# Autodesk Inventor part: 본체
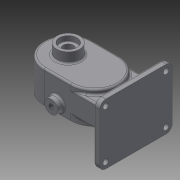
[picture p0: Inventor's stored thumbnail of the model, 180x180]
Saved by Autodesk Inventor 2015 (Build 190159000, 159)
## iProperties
Created: 2020-09
Part Number: 본체
Material: 일반
Document SubType Name: Modeling
Designer: LINEART-SSD.D4.16.07
Density: 1 g/cm^3
Appearance: 기본값
Author: LINEART-SSD.D4.16.07
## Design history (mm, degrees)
sketch "스케치1"
  geometry: L1 (0, 0)-(-44, 0); L2 (0, 40)-(-44, 40); L3 (-44, -40)-(0, -40); A1 r 40 centre (0, 0) between (0, -40) and (0, 40); A2 r 40 centre (-44, 0) between (-44, 40) and (-44, -40); 1 further point
  constraints: 8 end point, 4 point on circle, 4 tangent, 2 centre point, 1 horizontal, 1 midpoint, 1 parallel
  dimensions: "d0" = 80 diameter of A2; "d4" = 44 distance of L1.start L1.end
extrude "돌출1" new body sketch "스케치1" distance "d2" = 53; taper "d3" = 0 deg
sketch "스케치2"
  geometry: L1 (44, 0)-(0, 0); L2 (44, -24)-(0, -24); L3 (0, 24)-(44, 24); L4 (0, 40)-(44, 40) reference; A1 r 24 centre (44, 0) between (44, -24) and (44, 24); A2 r 24 centre (0, 0) between (0, 24) and (0, -24); A3 r 40 centre (0, 0) between (0, 40) and (0, -40) reference; A4 r 40 centre (44, 0) between (44, -40) and (44, 40) reference; 2 further points
  constraints: 8 end point, 4 point on circle, 4 tangent, 2 centre point, 1 horizontal, 1 midpoint, 1 parallel
  dimensions: "d5" = 24 radius of A1; "d6" = 44 distance of L1.start L1.end; "d7" = 40 distance from line of point (22, 0) L4; "d8" = 22 distance of point (22, 0) A4.centre
extrude "돌출2" cut sketch "스케치2" distance "d9" = 29; taper "d10" = 0 deg
sketch "스케치4"
  geometry: C1 r 19 at (-44, 0); A1 r 40 centre (-44, 0) between (-44, 40) and (-44, -40) reference; 1 further point
  constraints: 1 centre point, 1 coincident
  dimensions: "d22" = 38 diameter of C1
extrude "돌출3" join sketch "스케치4" distance "d23" = 17; taper "d24" = 0 deg
sketch "스케치5"
  geometry: L1 (44, 0)-(44, 0) reference; L2 (44, 0)-(44, 29) reference; L3 (44, 29)-(44, 29) reference; L4 (44, 0)-(44, 29) reference; L5 (63, 70)-(25, 70) reference; L6 (68, 29)-(44, 29) reference; L7 (44, 0)-(44, 70); L8 (56.5, 29)-(56.5, 44); L9 (56.5, 44)-(52.5, 44); L10 (52.5, 44)-(52.5, 62); L11 (52.5, 62)-(58, 62); L12 (58, 62)-(58, 69.3); L13 (58, 69.3)-(58.404, 70); L14 (56.5, 29)-(44, 29); L15 (58.404, 70)-(44, 70); L16 (44, 29)-(44, 70); 1 further point
  constraints: 20 end point, 6 perpendicular, 2 point on line, 1 collinear, 1 midpoint, 1 vertical
  dimensions: "d25" = 15 distance of L8.start L8.end; "d26" = 0.7 vertical distance of L12.end L13.end; "d27" = 30 deg angle of L12 L13; "d28" = 28 diameter of L12 L7; "d29" = 7.3 distance of L11.end L12.end; "d30" = 17 diameter of L10 L7; "d31" = 25 diameter of L8 L7
revolve "회전1" sketch "스케치5" stored, may be unused: angle "d32" = 90 deg
sketch "스케치6"
  geometry: C1 r 12.5 at (0, 0); 1 further point
  constraints: 1 centre point, 1 coincident
  dimensions: "d33" = 25 diameter of C1
extrude "돌출4" cut sketch "스케치6" distance "d34" = 15; taper "d35" = 0 deg
node "작업 평면2"
  node "작업 평면1"
sketch "스케치7"
  geometry: L1 (19, 70)-(-19, 70) reference; L2 (0, 70)-(60, 70); L3 (60, 70)-(60, -30); L4 (60, -30)-(-60, -30); L5 (-60, -30)-(-60, 70); L6 (-60, 70)-(0, 70); 1 further point
  constraints: 10 end point, 2 perpendicular, 1 collinear, 1 horizontal, 1 midpoint, 1 vertical
  dimensions: "d38" = 60 distance of L2.start L2.end; "d39" = 100 distance of L2.end L3.end; "d40" = 120 distance of L3.end L4.end
extrude "돌출5" join sketch "스케치7" distance "d41" = 10; taper "d42" = 0 deg
node "작업 평면3"
sketch "스케치8"
  geometry: L1 (0, 40)-(-44, 40) reference; L2 (-44, -40)-(0, -40) reference; L3 (58, -60)-(58, 60) reference; L4 (0, 40)-(58, 40); L5 (0, -40)-(58, -40); L6 (58, 40)-(58, -40); A1 r 40 centre (0, 0) between (0, -40) and (0, 40) reference; A2 r 40 centre (0, 0) between (0, -40) and (0, 40); 1 further point
  constraints: 6 end point, 3 tangent, 2 perpendicular, 2 point on circle, 2 point on line, 1 centre point, 1 collinear
extrude "돌출6" join sketch "스케치8" stored distance "d44" = 37; taper "d45" = 0 deg
fillet "모깎기1" dims "d46" = 3
fillet "모깎기2" dims "d47" = 3
sketch "스케치9"
  geometry: L1 (0, 0)-(44, 0) reference; C1 r 11 at (22, 14)
  constraints: 1 centre point
  dimensions: "d48" = 22 diameter of C1; "d49" = 14 distance from line of L1 C1.centre; "d50" = 22 horizontal distance of C1.centre L1.start
extrude "돌출7" join sketch "스케치9" distance "d51" = 10; taper "d52" = 0 deg
sketch "스케치10"
  geometry: C1 r 11 at (22, -14) reference; C2 r 11 at (22, -14); 1 further point
  constraints: 1 centre point, 1 coincident, 1 concentric
extrude "돌출8" join sketch "스케치10" distance "d53" = 10; taper "d54" = 0 deg
sketch "스케치11"
  geometry: C1 r 11 at (0, 0) reference; 2 further points
  constraints: 1 coincident
hole "구멍1" sketch "스케치11" at (0, 0) diameter "d55" = 8.376; stored, may be unused: countersink angle "d59" = 90 deg, drill point angle "d61" = 0 deg; dims "d56" = 20, "d57" = 4, "d58" = 2, "d60" = 27.3
sketch "스케치12"
  geometry: C1 r 11 at (0, 0) reference; 2 further points
  constraints: 1 coincident
hole "구멍2" sketch "스케치12" at (0, 0) diameter "d62" = 8.376; stored, may be unused: countersink angle "d66" = 90 deg, drill point angle "d68" = 0 deg; dims "d63" = 20, "d64" = 4, "d65" = 2, "d67" = 27.3
sketch "스케치13"
  geometry: C1 r 8.5 at (44, 0) reference; 2 further points
  constraints: 1 horizontal alignment
  dimensions: "d69" = 31 distance of C1.centre point (75, 0)
hole "구멍3" sketch "스케치13" at (75, 0) diameter "d70" = 4.134; stored, may be unused: countersink angle "d74" = 90 deg, drill point angle "d76" = 118 deg; dims "d71" = 10, "d72" = 4, "d73" = 2, "d75" = 12
sketch "스케치14"
  geometry: C1 r 8.5 at (44, 0) reference; 3 further points
  constraints: 2 vertical alignment
  dimensions: "d77" = 31 distance of point (44, 31) C1.centre; "d78" = 31 distance of C1.centre point (44, -31)
hole "구멍4" sketch "스케치14" at (44, 31), (44, -31) diameter "d79" = 4.134; stored, may be unused: countersink angle "d83" = 90 deg, drill point angle "d85" = 118 deg; dims "d80" = 10, "d81" = 4, "d82" = 2, "d84" = 12
fillet "모깎기3" dims "d92" = 3
chamfer "모따기1" distance "d93" = 1; stored, may be unused: second distance "d94" = 2, angle "d95" = 45 deg
fillet "모깎기4" dims "d96" = 0.5
fillet "모깎기5" dims "d97" = 3
fillet "모깎기6" dims "d98" = 10
sketch "스케치15"
  geometry: A1 r 10 centre (-20, -50) between (-30, -50) and (-20, -60) reference; 2 further points
  constraints: 1 coincident
hole "구멍5" sketch "스케치15" at (-20, -50) diameter "d99" = 9; stored, may be unused: countersink angle "d103" = 90 deg, drill point angle "d105" = 0 deg; dims "d100" = 10, "d101" = 4, "d102" = 2, "d104" = 12
sketch "스케치16"
  geometry: A1 r 10 centre (60, -50) between (60, -60) and (70, -50) reference; A2 r 10 centre (60, 50) between (70, 50) and (60, 60) reference; A3 r 10 centre (-20, 50) between (-20, 60) and (-30, 50) reference; 4 further points
  constraints: 3 coincident
hole "구멍6" sketch "스케치16" at (60, -50), (60, 50), (-20, 50) diameter "d112" = 9; stored, may be unused: countersink angle "d116" = 90 deg, drill point angle "d118" = 0 deg; dims "d113" = 10, "d114" = 4, "d115" = 2, "d117" = 12
sketch "스케치17"
  geometry: L1 (60, 60)-(-20, 60) reference; L2 (-30, 50)-(-30, -50) reference; 2 further points
  constraints: 1 other
  dimensions: "d119" = 60 distance from line of L1 point (-18, 0); "d120" = 12 distance from line of L2 point (-18, 0)
feature "엠보싱1" sketch "스케치17" dims "d121" = 0.5, "d122" = 0
fillet "모깎기7" dims "d123" = 3
node "솔리드1"
pattern_linear "직사각형 패턴1" dims "d88" = 44
pattern_linear "직사각형 패턴2" dims "d91" = 106
node "투영된 루프1"
other parameters: "d36" = -22, "d43" = 26.5
